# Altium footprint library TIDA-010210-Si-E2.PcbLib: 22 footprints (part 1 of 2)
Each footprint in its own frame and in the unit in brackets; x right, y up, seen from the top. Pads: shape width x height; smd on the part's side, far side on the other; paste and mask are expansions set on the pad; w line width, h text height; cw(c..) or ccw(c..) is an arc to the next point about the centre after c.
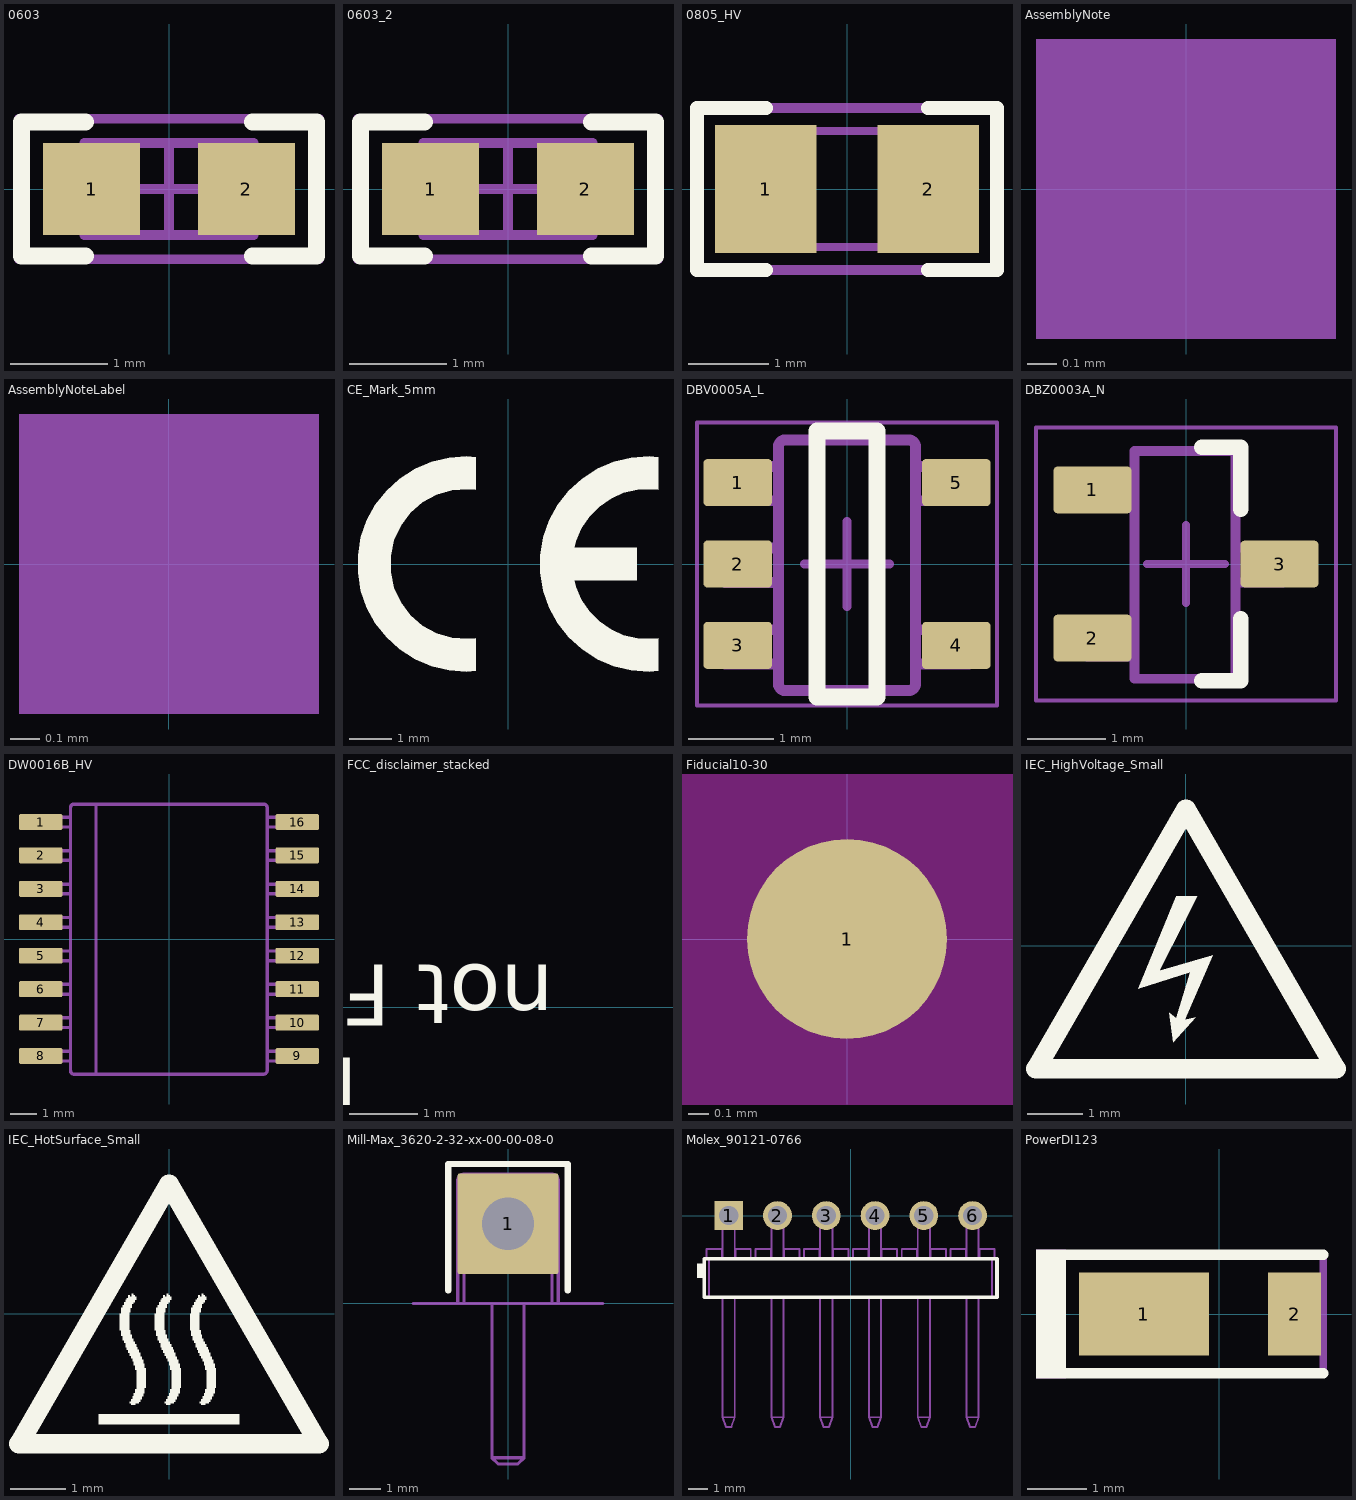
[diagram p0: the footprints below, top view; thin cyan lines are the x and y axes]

## 0603 [mm] "0603 from SM-752 data"
height 1
pads (2):
  rect 1x0.95 smd: 1(-0.8,0) 2(0.8,0)
Top Overlay:
  lines w0.178: -0.864,-0.691 -1.524,-0.691 -1.524,0.693 -0.864,0.693 ; 0.864,-0.691 1.524,-0.691 1.524,0.693 0.864,0.693
Mechanical 5:
  lines w0.1: -1.55,-0.725 -1.55,0.725 1.55,0.725 1.55,-0.725 -1.55,-0.725
  text ".Designator" at -1.397,-0.381 h0.76
Mechanical 13:
  lines w0.1: -0.55,-0.475 -0.55,0.475 ; 0.55,-0.475 0.55,0.475 ; -0.875,-0.475 0.875,-0.475 0.875,0.475 -0.875,0.475 -0.875,-0.475
Mechanical 15:
  lines w0.1: -0.475,0 0.475,0 ; 0,-0.475 0,0.475 ; -1.55,-0.725 1.55,-0.725 1.55,0.725 -1.55,0.725 -1.55,-0.725
3D body: height 1, standoff 0, extent -0.874,-0.474 -0.551,0.474
3D body: height 1, standoff 0, extent -0.549,-0.474 0.549,0.474
3D body: height 1, standoff 0, extent 0.551,-0.474 0.874,0.474

## 0603_2 [mm]
pads (2):
  rect 1x0.95 smd: 1(-0.8,0) 2(0.8,0)
Top Overlay:
  lines w0.178: -0.864,-0.691 -1.524,-0.691 -1.524,0.693 -0.864,0.693 ; 0.864,-0.691 1.524,-0.691 1.524,0.693 0.864,0.693
Mechanical 5:
  lines w0.1: -1.55,-0.725 1.55,-0.725 1.55,0.725 -1.55,0.725 -1.55,-0.725
  text ".Designator" at 0.457,0.315 h0.46
Mechanical 13:
  lines w0.1: -0.55,-0.475 -0.55,0.475 ; 0.55,-0.475 0.55,0.475 ; -0.875,-0.475 -0.875,0.475 0.875,0.475 0.875,-0.475 -0.875,-0.475
Mechanical 15:
  lines w0.1: -0.475,0 0.475,0 ; 0,-0.475 0,0.475 ; -1.55,-0.725 -1.55,0.725 1.55,0.725 1.55,-0.725 -1.55,-0.725
3D body: height 1, standoff 0, extent 0.551,-0.474 0.874,0.474
3D body: height 1, standoff 0, extent -0.549,-0.474 0.549,0.474
3D body: height 1, standoff 0, extent -0.874,-0.474 -0.551,0.474

## 0805_HV [mil] "0805 with 30mil clearance between pads"
height 57.09
pads (2):
  rect 50x63 smd: 1(-40,0) 2(40,0)
Top Overlay:
  lines w7: -40,-40 -74,-40 -74,0 -74,40 -40,40 ; 40,-40 74,-40 74,0 74,40 40,40
Mechanical 5:
  lines w5: -74,-40 -74,40 74,40 74,-40 -74,-40
  text ".Designator" at -64,-17 h35
Mechanical 13:
  lines w3.94: -25.59,-28.54 -25.59,28.54 ; 25.59,-28.54 25.59,28.54 ; -43.31,-28.54 -43.31,28.54 43.31,28.54 43.31,-28.54 -43.31,-28.54
3D body: height 57.09, standoff 0, extent 25.61,-28.52 43.29,28.52
3D body: height 57.09, standoff 0, extent -25.57,-28.52 25.57,28.52
3D body: height 57.09, standoff 0, extent -43.29,-28.52 -25.61,28.52

## AssemblyNote [mm] "Assembly Note"
Mechanical 5:
  rectangle: -0.508,-0.508 0.508,0.508
  text ".Comment" at 1.143,-0.508 h0.46
  text ".Designator" at -4.191,-0.508 h0.46

## AssemblyNoteLabel [mm] "Assembly Note for PCB Labels"
Mechanical 5:
  rectangle: -0.508,-0.508 0.508,0.508
  text "Install label in silkscreened box after final wash.  Text shall be 8 pt font.  Text shall be per the Label Table in the PDF schematic." at 1.143,-0.508 h0.46
  text ".Designator" at -4.191,-0.508 h0.46

## CE_Mark_5mm [mm] "Minimum text height for CE Mark"
Top Overlay:
  region: 3.5,-1.732 3.337,-1.748 3.01,-1.733 2.691,-1.658 2.392,-1.525 2.123,-1.339 1.894,-1.106 1.712,-0.834 1.583,-0.533 1.541,-0.375 3,-0.375 3,0.375 1.541,0.375 1.583,0.533 1.712,0.834 1.894,1.106 2.123,1.339 2.392,1.526 2.691,1.658 3.01,1.733 3.337,1.748 3.5,1.732 3.5,2.487 3.292,2.508 2.874,2.48 2.467,2.383 2.081,2.22 1.728,1.994 1.418,1.714 1.158,1.385 0.957,1.018 0.82,0.622 0.75,0.209 0.75,-0.209 0.82,-0.622 0.957,-1.018 1.158,-1.385 1.418,-1.714 1.728,-1.994 2.081,-2.22 2.467,-2.383 2.874,-2.48 3.292,-2.508 3.5,-2.487
  region: -0.75,-2.487 -0.958,-2.508 -1.376,-2.48 -1.783,-2.383 -2.169,-2.22 -2.522,-1.994 -2.832,-1.714 -3.092,-1.385 -3.293,-1.018 -3.43,-0.622 -3.5,-0.209 -3.5,0.209 -3.43,0.622 -3.293,1.018 -3.092,1.385 -2.832,1.714 -2.522,1.994 -2.169,2.22 -1.783,2.383 -1.376,2.48 -0.958,2.508 -0.75,2.487 -0.75,1.732 -0.937,1.749 -1.31,1.722 -1.669,1.617 -1.998,1.438 -2.281,1.193 -2.505,0.893 -2.66,0.553 -2.74,0.187 -2.74,-0.187 -2.66,-0.553 -2.505,-0.893 -2.281,-1.193 -1.998,-1.438 -1.669,-1.617 -1.31,-1.722 -0.937,-1.749 -0.75,-1.732

## DBV0005A_L [mm] "SOT23, 5-Leads, Body 2.9x1.6mm, Pitch 0.95mm, Lead Span 2.8mm, IPC High Density"
height 1.45
pads (5):
  rrect18% 0.8x0.55 smd: 1(-1.275,0.95) 2(-1.275,0) 3(-1.275,-0.95) 4(1.275,-0.95) 5(1.275,0.95)
Top Overlay:
  lines w0.2: -0.35,-1.55 0.35,-1.55 0.35,1.55 -0.35,1.55 -0.35,-1.55
Mechanical 5:
  lines w0.127: -0.801,1.371 cw(c-0.725,1.37) -0.725,1.446 ; -0.801,1.37 -0.801,-1.399 -0.801,-1.4 ccw(c-0.725,-1.399) -0.725,-1.475 ; -0.801,1.37 -0.801,1.371 ; -0.725,-1.475 -0.725,-1.475 ; -0.725,-1.475 0.723,-1.475 0.724,-1.475 ccw(c0.723,-1.399) 0.799,-1.4 0.799,-1.399 0.799,1.37 ; -0.725,1.446 0.723,1.446 0.724,1.446 cw(c0.723,1.37) 0.799,1.371 ; -0.725,1.446 -0.725,1.446 ; 0.799,1.37 0.799,1.371 ; -1.423,-1.167 -1.199,-1.167 -1.105,-1.167 -1.088,-1.167 -0.835,-1.167 -0.801,-1.167 -0.801,-0.767 -0.835,-0.767 -1.088,-0.767 -1.105,-0.767 -1.199,-0.767 -1.423,-0.767 -1.423,-1.167 ; -1.423,-0.215 -1.199,-0.215 -1.105,-0.215 -1.088,-0.215 -0.835,-0.215 -0.801,-0.215 -0.801,0.186 -0.835,0.186 -1.088,0.186 -1.105,0.186 -1.199,0.186 -1.423,0.186 -1.423,-0.215 ; -1.423,0.738 -1.199,0.738 -1.105,0.738 -1.088,0.738 -0.835,0.738 -0.801,0.738 -0.801,1.138 -0.835,1.138 -1.088,1.138 -1.105,1.138 -1.199,1.138 -1.423,1.138 -1.423,0.738 ; 0.799,-1.167 0.799,-0.767 0.834,-0.767 1.087,-0.767 1.103,-0.767 1.198,-0.767 1.422,-0.767 1.422,-1.167 1.198,-1.167 1.103,-1.167 1.087,-1.167 0.834,-1.167 0.799,-1.167 ; 0.799,0.738 0.799,1.138 0.834,1.138 1.087,1.138 1.103,1.138 1.198,1.138 1.422,1.138 1.422,0.738 1.198,0.738 1.103,0.738 1.087,0.738 0.834,0.738 0.799,0.738
  text ".Designator" at -0.184,-0.172 h0.46
Mechanical 15:
  lines w0.05: -1.75,-1.65 -1.75,1.65 1.75,1.65 1.75,-1.65 -1.75,-1.65
  lines w0.1: -0.5,0 0.5,0 ; 0,-0.5 0,0.5
3D body "DBV0005A.stp": height 1.09, standoff 0, extent -1.422,-1.46 1.422,1.461

## DBZ0003A_N [mm] "SOT23, 3-Leads, Body 2.9x1.3mm, Pitch 0.95mm, Lead Span 2.4mm, IPC Medium Density"
height 1.12
pads (3):
  rrect17% 1x0.6 smd: 1(-1.2,0.95) 2(-1.2,-0.95) 3(1.2,0)
Top Overlay:
  lines w0.2: 0.2,-1.5 0.7,-1.5 0.7,-0.7 ; 0.2,1.5 0.7,1.5 0.7,0.7
Mechanical 5:
  lines w0.127: -1.27,-1.187 -1.27,-0.743 -1.063,-0.743 -1.005,-0.743 -0.814,-0.743 -0.66,-0.743 -0.66,-1.187 -0.814,-1.187 -1.005,-1.187 -1.063,-1.187 -1.27,-1.187 ; -1.27,0.718 -1.27,1.162 -1.063,1.162 -1.005,1.162 -0.814,1.162 -0.66,1.162 -0.66,0.718 -0.814,0.718 -1.005,0.718 -1.063,0.718 -1.27,0.718 ; -0.66,-1.473 -0.66,1.448 0.635,1.448 0.635,-1.473 -0.66,-1.473 ; 0.635,-0.235 0.789,-0.235 0.98,-0.235 1.037,-0.235 1.245,-0.235 1.245,0.21 1.037,0.21 0.98,0.21 0.789,0.21 0.635,0.21 0.635,-0.235
  text ".Designator" at -0.178,-0.127 h0.46
Mechanical 15:
  lines w0.05: -1.925,-1.75 1.925,-1.75 1.925,1.75 -1.925,1.75 -1.925,-1.75
  lines w0.1: -0.5,0 0.5,0 ; 0,-0.5 0,0.5
3D body "DBZ0003A.stp": height 0.98, standoff 0, extent -1.257,-1.46 1.257,1.461

## DW0016B_HV [mm] "SOIC-16, HV/isolation option"
height 2.65
pads (16):
  rrect17% 1.65x0.6 smd: 1(-4.875,4.445) 2(-4.875,3.175) 3(-4.875,1.905) 4(-4.875,0.635) 5(-4.875,-0.635) 6(-4.875,-1.905) 7(-4.875,-3.175) 8(-4.875,-4.445) 9(4.875,-4.445) 10(4.875,-3.175) 11(4.875,-1.905) 12(4.875,-0.635) 13(4.875,0.635) 14(4.875,1.905) 15(4.875,3.175) 16(4.875,4.445)
Mechanical 5:
  lines w0.1: -2.775,-5.135 -2.775,5.127
  lines w0.127: -3.74,-4.633 -5.15,-4.633 -5.15,-4.265 -3.74,-4.265 ; -3.74,-3.363 -5.15,-3.363 -5.15,-2.995 -3.74,-2.995 ; -3.74,-2.093 -5.15,-2.093 -5.15,-1.725 -3.74,-1.725 ; -3.74,-0.823 -5.15,-0.823 -5.15,-0.455 -3.74,-0.455 ; -3.74,0.447 -5.15,0.447 -5.15,0.815 -3.74,0.815 ; -3.74,1.717 -5.15,1.717 -5.15,2.085 -3.74,2.085 ; -3.74,2.987 -5.15,2.987 -5.15,3.355 -3.74,3.355 ; -3.74,4.257 -5.15,4.257 -5.15,4.625 -3.74,4.625 ; 3.74,-4.633 5.15,-4.633 5.15,-4.265 3.74,-4.265 ; 3.74,-3.363 5.15,-3.363 5.15,-2.995 3.74,-2.995 ; 3.74,-2.093 5.15,-2.093 5.15,-1.725 3.74,-1.725 ; 3.74,-0.823 5.15,-0.823 5.15,-0.455 3.74,-0.455 ; 3.74,0.447 5.15,0.447 5.15,0.815 3.74,0.815 ; 3.74,1.717 5.15,1.717 5.15,2.085 3.74,2.085 ; 3.74,2.987 5.15,2.987 5.15,3.355 3.74,3.355 ; 3.74,4.257 5.15,4.257 5.15,4.625 3.74,4.625 ; -3.74,-5.008 ccw(c-3.613,-5.008) -3.614,-5.135 3.601,-5.135 ccw(c3.6,-5.008) 3.727,-5.008 3.727,5 ccw(c3.6,5) 3.601,5.127 -3.614,5.127 ccw(c-3.613,5) -3.74,5 -3.74,-5.008
  text ".Designator" at -0.425,1.85 h1.02
3D body "DW0016B.stp": height 2.59, standoff 0, extent -5.167,-5.15 5.167,5.15

## FCC_disclaimer_stacked [mm]
Top Overlay:
  text "For evaluation only;" at 6.238,-0.445 h1.52
  text "not FCC approved for resale." at 9.092,0.911 h1.52

## Fiducial10-30 [mm]
height 19.05
pads (1):
  round 1 smd mask+1: 1(0,0)
Top Layer keep-out:
  circle w1.678: c0,0 r0.75

## IEC_HighVoltage_Small [mm]
Top Overlay:
  region: -0.178,0.889 0.203,0.889 -0.483,-0.457 0.483,-0.178 -0.025,-1.346 0.178,-1.295 -0.229,-1.753 -0.305,-1.219 -0.178,-1.321 0.076,-0.483 -0.864,-0.787
  lines w0.356: -2.718,-2.235 2.718,-2.235 0,2.472 -2.718,-2.235

## IEC_HotSurface_Small [mm]
height 19.05
Top Overlay:
  drawing of 10 lines, arcs and shapes, not listed

## Mill-Max_3620-2-32-xx-00-00-08-0 [mm] "PCB Pin, 0.04\" DIA, R/A, Edge-Mount"
height 0.635
pads (1):
  rrect3% 3.18x3.18 hole 1.65: 1(0,2.52)
Top Overlay:
  lines w0.2: -1.89,0.41 -1.89,4.41 1.89,4.41 1.89,0.41
Mechanical 1:
  lines w0.1: -3,0 3,0
Mechanical 5:
  lines w0.1: -0.51,0 -0.51,-4.88 ; 0.51,0 0.51,-4.88 ; -1.59,3.89 cw(c-1.39,3.89) -1.39,4.09 ; -1.59,3.89 -1.59,0 -1.39,0 ; -1.59,3.89 -1.39,3.89 ; -1.39,0 -1.39,3.89 ; -1.39,0 1.39,0 ; -1.39,3.89 1.39,3.89 ; -1.39,3.89 -1.39,4.09 ; -1.39,4.09 1.39,4.09 ; -0.51,-4.88 0.51,-4.88 ; -0.51,-4.88 -0.31,-5.08 0.31,-5.08 0.51,-4.88 ; 1.39,0 1.59,0 1.59,3.89 ; 1.39,0 1.39,3.89 ; 1.39,3.89 1.39,4.09 ; 1.39,3.89 1.59,3.89 ; 1.39,4.09 cw(c1.39,3.89) 1.59,3.89
  text ".Designator" at -0.785,2.21 h0.46
3D body "3620-2-32-xx-00-00-08-0.stp": height 0.65, standoff -2.53, extent -1.59,-5.06 1.59,4.11

## Molex_90121-0766 [mm] "Header, 2.54mm, 6x1, R/A, TH"
height 3.6
pads (6):
  rect 1.5x1.5 hole 1: 1(-6.35,0)
  round 1.5 hole 1: 2(-3.81,0) 3(-1.27,0) 4(1.27,0) 5(3.81,0) 6(6.35,0)
Top Overlay:
  rectangle: -8,-3.25 -7.62,-2.5
  lines w0.2: -7.62,-4.25 -7.37,-4.25 -5.469,-4.25 -5.175,-4.25 -4.985,-4.25 -4.691,-4.25 -2.929,-4.25 -2.635,-4.25 -2.445,-4.25 -2.151,-4.25 -0.389,-4.25 -0.095,-4.25 0.095,-4.25 0.389,-4.25 2.151,-4.25 2.445,-4.25 2.635,-4.25 2.929,-4.25 4.691,-4.25 4.985,-4.25 5.175,-4.25 5.469,-4.25 7.37,-4.25 7.62,-4.25 7.62,-2.25 -7.62,-2.25 -7.62,-4.25
Mechanical 5:
  drawing of 200 lines, arcs and shapes, not listed
  text ".Designator" at -0.864,-2.972 h0.46
3D body "901210766.stp": height 3.63, standoff -2.87, extent -7.62,-11 7.62,0.318

## PowerDI123 [mm] "Diodes Inc recommended land pattern, document number DS30628 Rev. 6-2"
height 1
pads (2):
  rect 2.2x1.4 smd: 1(-1.275,0)
  rect 0.9x1.4 smd: 2(1.275,0)
Top Overlay:
  rectangle: -3.099,-1.092 -2.591,1.092
  lines w0.178: -2.946,-1.003 1.759,-1.003 ; -2.946,1.003 1.759,1.003
Mechanical 5:
  rectangle: -3.099,-1.092 -2.591,1.092
  lines w0.127: -2.946,-1.003 1.759,-1.003 1.759,1.003 -2.946,1.003
  text ".Designator" at -0.737,0.457 h0.46
3D body "PowerDI123.stp": height 1, standoff 0, extent -2.375,-0.965 1.525,0.965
